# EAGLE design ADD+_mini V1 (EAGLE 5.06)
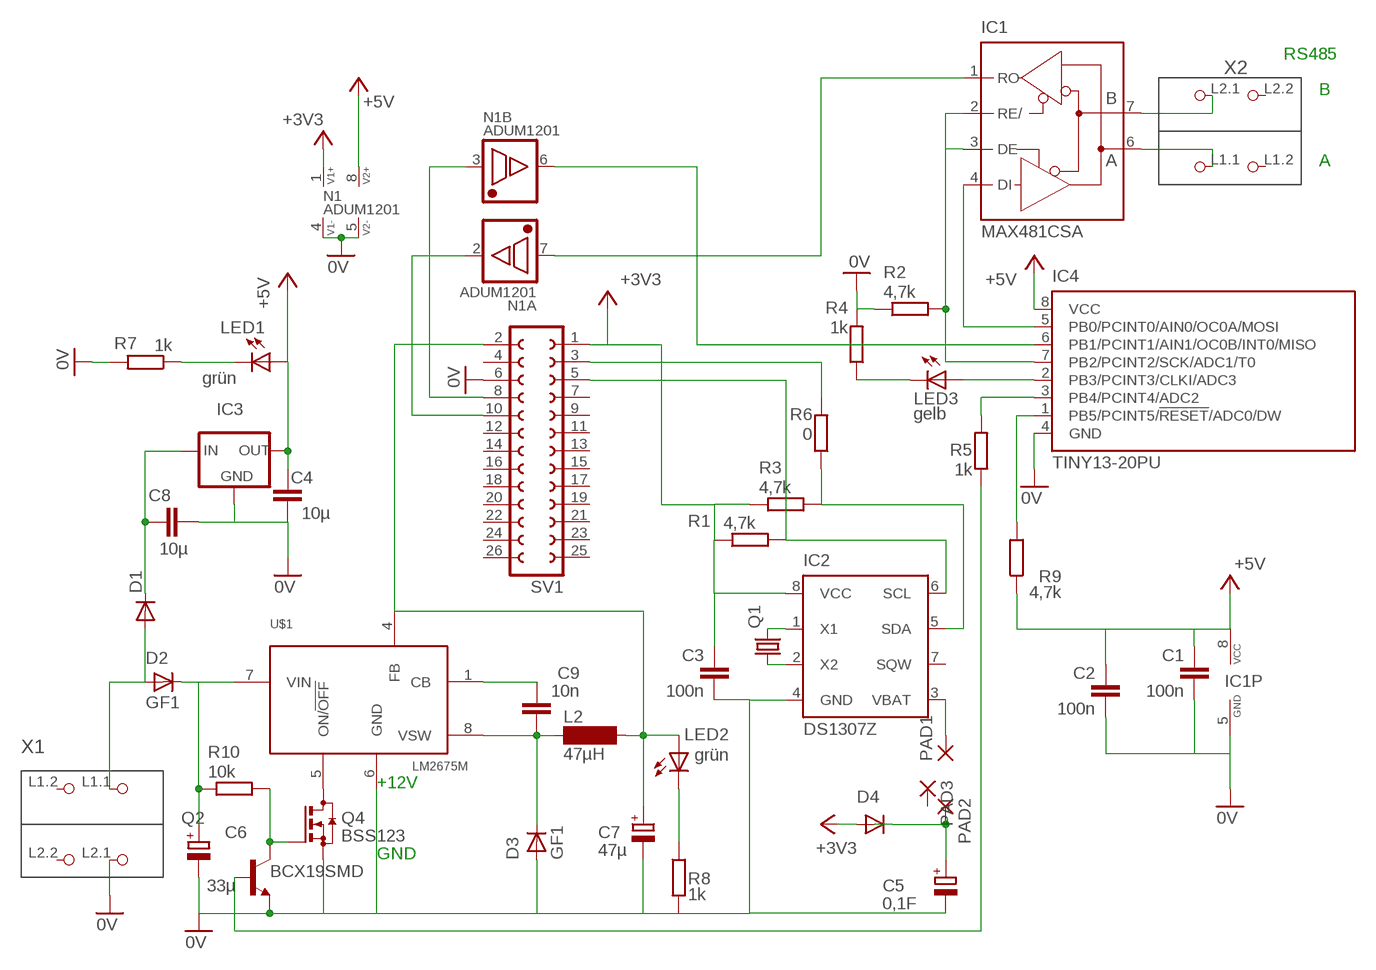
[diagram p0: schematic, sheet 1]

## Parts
C1  100n  C-EUC0603  [C0603]
C2  100n  C-EUC0603  [C0603]
C3  100n  C-EUC1206  [C1206]
C4  10µ  C-EUC1206K  [C1206K]
C5  0,1F  CPOL-EUE5-13  [E5-13]
C6  33µ  CPOL-EUSMCD  [SMC_D]
C7  47µ  CPOL-EUSMCD  [SMC_D]
C8  10µ  C-EUC1206K  [C1206K]
C9  10n  C-EUC0603  [C0603]
D1  DIODE-SOD323-W  [SOD323-W]
D2  GF1  [SMA-DO214AC]
D3  GF1  [SMA-DO214AC]
D4  DIODE-SOD323-W  [SOD323-W]
IC1  MAX481CSA  [SO08]
IC2  DS1307Z  [SOIC8]
IC3  78XXS  [78XXS]
IC4  TINY13-20PU  [DIL08]
L2  47µH  BS11  [BS11]
LED1  grün  LEDCHIPLED_0603  [CHIPLED_0603]
LED2  grün  LEDCHIPLED_0603  [CHIPLED_0603]
LED3  gelb  LEDCHIPLED_0603  [CHIPLED_0603]
N1  ADUM1201  [SO08]
PAD1  2,15/1,0  [2,15/1,0]
PAD2  2,15/1,0  [2,15/1,0]
PAD3  2,15/1,0  [2,15/1,0]
Q1  CRYSTALTC38H  [TC38H]
Q2  BCX19SMD  [SOT23-BEC]
Q4  BSS123  [SOT23]
R1  4,7k  R-EU_R0603  [R0603]
R2  4,7k  R-EU_R0603  [R0603]
R3  4,7k  R-EU_R0603  [R0603]
R4  1k  R-EU_R0603  [R0603]
R5  1k  R-EU_R0603  [R0603]
R6  0  R-EU_R1206  [R1206]
R7  1k  R-EU_R0603  [R0603]
R8  1k  R-EU_R0603  [R0603]
R9  4,7k  R-EU_R0603  [R0603]
R10  10k  R-EU_R0603  [R0603]
SV1  FE13-2  [FE13-2]
U$1  LM2675M  [SO08]
X1  2060-402/998-404  [P-2060-402/998-404]
X2  2060-402/998-404  [P-2060-402/998-404]

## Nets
0V: C1.2 C2.2 C3.2 C4.2 C5.- C6.- C7.- C8.1 D3.A IC1.5(GND) IC2.4(GND) IC3.GND IC4.4(GND) N1.4(P:V1-) N1.5(P:V2-) Q2.E Q4.2(S) R2.1 R4.2 R7.2 R8.2 SV1.6 U$1.6(GND) X1.L2.1(P2.1)
+3V3: C3.1 D4.A IC2.8(VCC) N1.1(P:V1+) R1.1 R3.1 SV1.1
+5V: C1.1 C2.1 C4.1 IC1.8(VCC) IC3.OUT IC4.8(VCC) LED1.A N1.8(P:V2+) R9.1
N$2: D1.A D2.A X1.L1.1(P1.1)
N$3: C5.+ D4.C PAD2.1(P)
N$4: IC2.2(X2) Q1.1
N$6: IC1.1(RO) N1.7(A:IN)
N$7: C6.+ D2.K(C) R10.2 U$1.7(VIN)
N$8: Q4.3(D) U$1.5(ON/!OFF)
N$9: IC2.5(SDA) R3.2 R6.1
N$10: C8.2 D1.C IC3.IN
N$11: IC2.6(SCL) R1.2 SV1.5
N$12: IC2.1(X1) Q1.2
N$13: IC4.6(PB1/PCINT1/AIN1/OC0B/INT0/MISO) N1.6(B:OUT)
N$14: IC1.4(DI) IC4.5(PB0/PCINT0/AIN0/OC0A/MOSI)
N$15: IC1.2(RE/) IC1.3(DE) IC4.7(PB2/PCINT2/SCK/ADC1/T0) R2.2
N$16: LED2.C R8.1
N$17: R6.2 SV1.3
N$18: IC1.7(B) X2.L2.1(P2.1)
N$19: IC4.3(PB4/PCINT4/ADC2) R5.2
N$20: IC4.1(PB5/PCINT5/!RESET!/ADC0/DW) R9.2
N$21: Q2.B R5.1
N$22: N1.2(A:OUT) SV1.10
N$23: N1.3(B:IN) SV1.8
N$24: IC2.3(VBAT) PAD1.1(P)
N$25: Q2.C Q4.1(G) R10.1
N$26: IC1.6(A) X2.L1.1(P1.1)
N$28: C9.2 D3.K(C) L2.1 U$1.8(VSW)
N$29: LED1.C R7.1
N$30: C9.1 U$1.1(CB)
N$31: C7.+ L2.2 LED2.A SV1.2 U$1.4(FB)
N$32: IC4.2(PB3/PCINT3/CLKI/ADC3) LED3.A
N$33: LED3.C R4.1
Unconnected: IC2.7(SQW) PAD3.1(P) SV1.4 SV1.7 SV1.9 SV1.11 SV1.12 SV1.13 SV1.14 SV1.15 SV1.16 SV1.17 SV1.18 SV1.19 SV1.20 SV1.21 SV1.22 SV1.23 SV1.24 SV1.25 SV1.26 X1.L1.2(P1.2) X1.L2.2(P2.2) X2.L1.2(P1.2) X2.L2.2(P2.2)

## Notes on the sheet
- RS485
- B
- A
- +12V
- GND

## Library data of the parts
C1-C4 C8 C9 = rcl:C-EU: CAPACITOR, European symbol
C5-C7 = rcl:CPOL-EU: POLARIZED CAPACITOR, European symbol
D1 D4 = diode:DIODE-: DIODE
D2 D3 = diode:GF1: DIODE
IC1 = maxim:MAX481CSA: RS485 TRANSEIVER
IC2 = ds1307_pcf8583:DS1307: I2C-Bus CLOCK/CALENDAR
IC3 = LM2675:78XXS: VOLTAGE REGULATOR
IC4 = atmel:TINY13: 8-bit AVR Microcontroller with 1K Bytes In-System Programmable Flash Source: http://www.atmel.com/dyn/resources/prod_documents/2535S.pdf
L2 = inductor-neosid:BS: INDUCTOR
LED1-LED3 = led:LED: LED
N1 = digital:ADUM1201: ADuM1400: 1+1 channel digital isolator (Analog Devices) +5V, 1Mbps
PAD1-PAD3 = wirepad:2,15/1,0: THROUGH-HOLE PAD
Q1 = crystal:CRYSTAL: CRYSTAL
Q2 = transistor-npn:BCX19*: NPN Transistor
Q4 = transistor-small-signal:BSS123: N-CHANNEL MOS FET
R1-R10 = rcl:R-EU_: RESISTOR, European symbol
SV1 = con-lsta:FE13-2: FEMALE HEADER
U$1 = Labor:LM2675: SIMPLE SWITCHER ® Power Converter High Efficiency 1A Step-Down Voltage Regulator General Description The LM2675 series of regulators are monolithic integrated circuits built with a LMDMOS process. These regulators provide all the active functions for a step-down (buck) switching regulator, capable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
X1 X2 = con-wago_2060:2060-402/998-404: Serie 2060, SMD-Leiterplattenklemme mit Betätigungsdrückern im Gurt 2-polig / Series 2060, SMD terminal block with push-buttons in tape-and-reel packing 2-pole Polzahl / Pole No.: 2 Bemessungsspannung / Rated Voltage: 160 V Nennstrom / Nominal Current: 9 A Leiterquerschnitt / Conductor Size: 0.2 -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

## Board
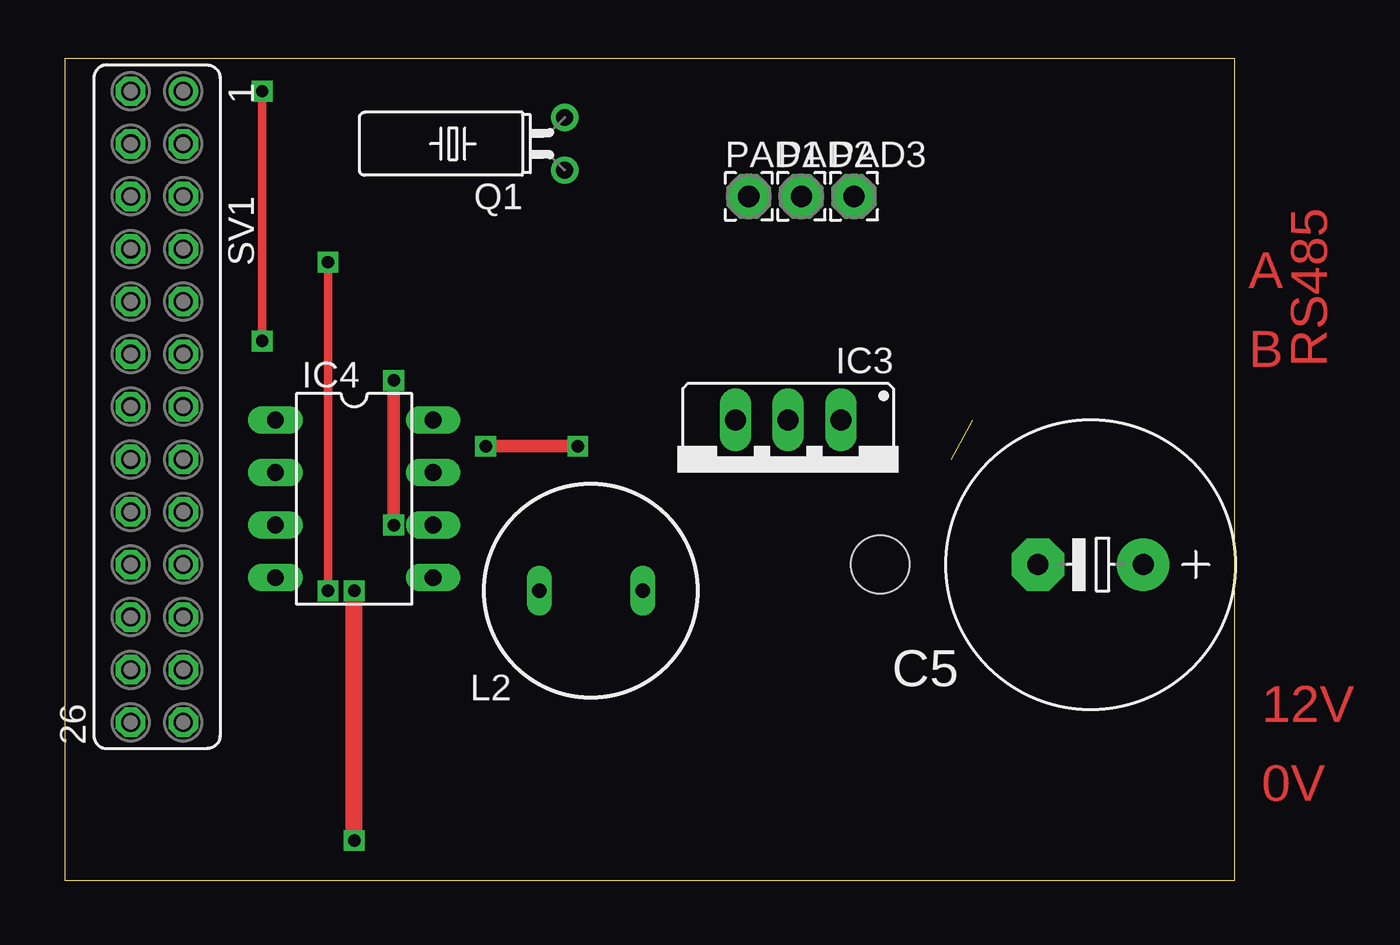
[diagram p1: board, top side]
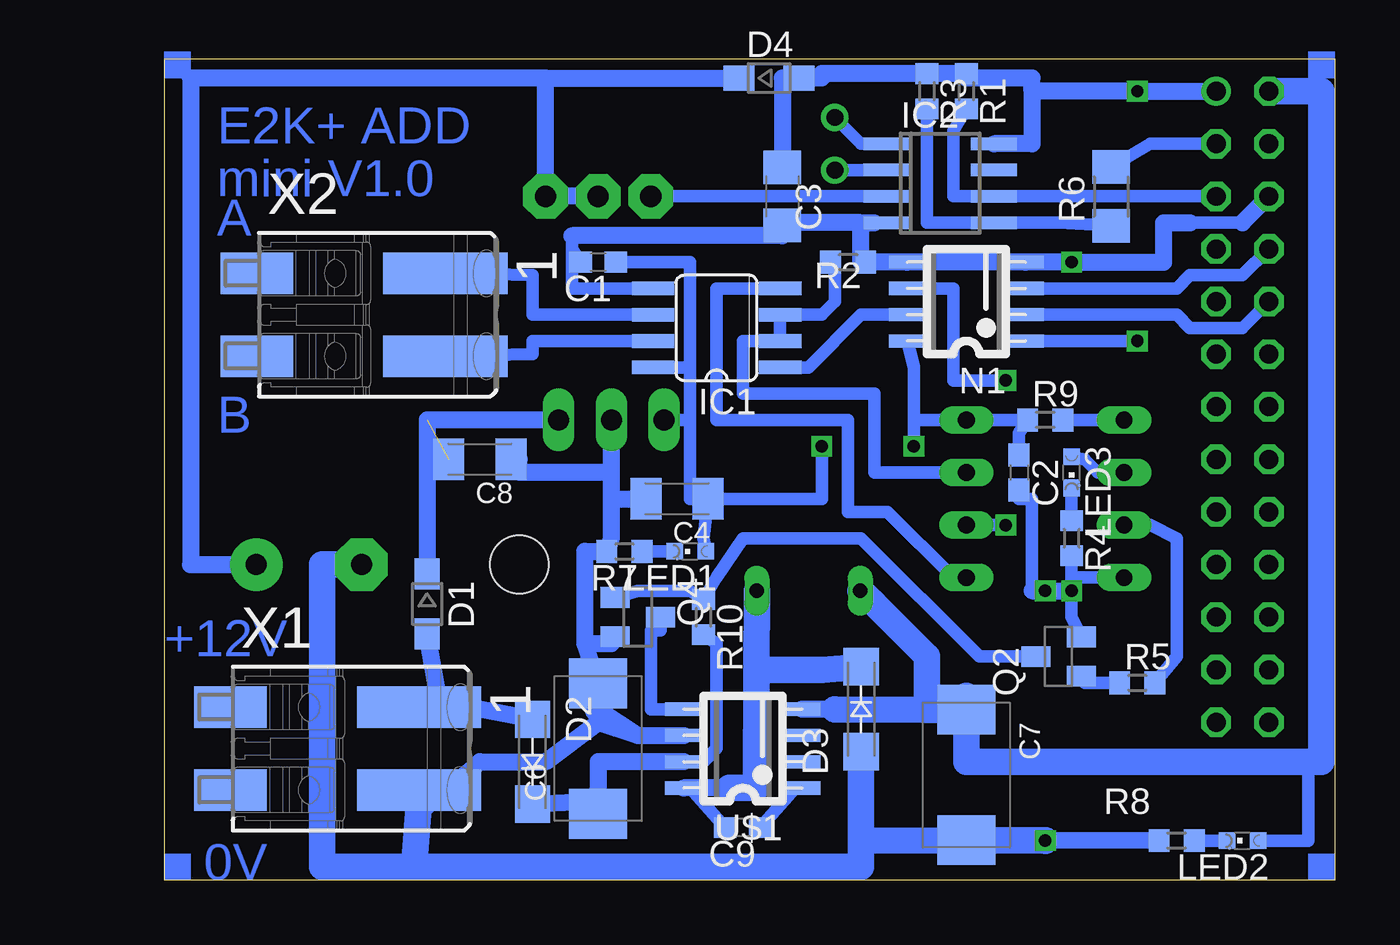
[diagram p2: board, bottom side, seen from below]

Size 56.49 x 39.68 mm. Coordinates in mm from the lower left corner, seen from the top.
Outline: 0,0 56.49,0 56.49,39.68 0,39.68 0,0
Copper layers (1*16): Top 0.035mm / dielectric 1.5mm / Bottom 0.035mm
Design rules "default": minimum track width 10mil, minimum drill 24mil, track to track 8mil, track to pad 8mil, pad to pad 8mil, via to via 8mil, smd to smd 8mil, copper to edge 40mil, drill to drill 8mil, minimum pad ring 10mil, minimum via ring 8mil, stop-mask expansion 4mil, vias tented up to drill 0mil, thermal gap 10mil
Holes 2.8 mm at 39.37,15.24

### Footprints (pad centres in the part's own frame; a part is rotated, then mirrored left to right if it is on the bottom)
C0603 = smd 1.1 x 1: 1 -0.85,0; 2 0.85,0
C1206 = smd 1.6 x 1.8: 1 -1.4,0; 2 1.4,0
C1206K = smd 1.5 x 2: 1 -1.5,0; 2 1.5,0
E5-13 = drill 1.016 pad 2.54 round: + -2.54,0 | drill 1.016 pad 2.54 octagon: - 2.54,0
SMC_D = smd 2.4 x 2.8: + -3.15,0; - 3.15,0
SOD323-W = smd 1.5 x 1.2: A 1.45,0; C -1.45,0
SMA-DO214AC = smd 1.8 x 1.7: A -2.05,0; K 2.05,0
SO08 = smd 0.66 x 2.032: 1 -1.905,-3.073; 2 -0.635,-3.073; 3 0.635,-3.073; 4 1.905,-3.073; 5 1.905,3.073; 6 0.635,3.073; 7 -0.635,3.073; 8 -1.905,3.073
SOIC8 = smd 0.6 x 2.2: 1 -1.905,-2.6; 2 -0.635,-2.6; 3 0.635,-2.6; 4 1.905,-2.6; 5 1.905,2.6; 6 0.635,2.6; 7 -0.635,2.6; 8 -1.905,2.6
78XXS = drill 1.016 long: GND 0,-2.54; IN -2.54,-2.54; OUT 2.54,-2.54
DIL08 = drill 0.813 long: 1 -3.81,-3.81; 2 -1.27,-3.81; 3 1.27,-3.81; 4 3.81,-3.81; 5 3.81,3.81; 6 1.27,3.81; 7 -1.27,3.81; 8 -3.81,3.81
BS11 = drill 0.7 long: 1 -2.5,0; 2 2.5,0
CHIPLED_0603 = smd 0.8 x 0.8: A 0,-0.75; C 0,0.75
SO08' = smd 0.635 x 1.778: 1 -1.905,-2.857; 2 -0.635,-2.857; 3 0.635,-2.857; 4 1.905,-2.857; 5 1.905,2.857; 6 0.635,2.857; 7 -0.635,2.857; 8 -1.905,2.857
2,15/1,0 = drill 1.016 pad 2.159 octagon: 1 0,0
TC38H = drill 0.813 round: 1 -1.27,0; 2 1.27,0
SOT23-BEC = smd 1 x 1.4: B -0.95,-1.1; C 0,1.1; E 0.95,-1.1
SOT23 = smd 1 x 1.4: 1 -0.95,-1.1; 2 0.95,-1.1; 3 0,1.1
R0603 = smd 1 x 1.1: 1 -0.85,0; 2 0.85,0
R1206 = smd 1.6 x 1.803: 1 -1.422,0; 2 1.422,0
FE13-2 = drill 0.914 round: 1 -15.24,1.27 | drill 0.914 octagon: 2 -15.24,-1.27; 3 -12.7,1.27; 4 -12.7,-1.27; 5 -10.16,1.27; 6 -10.16,-1.27; 7 -7.62,1.27; 8 -7.62,-1.27; 9 -5.08,1.27; 10 -5.08,-1.27; 11 -2.54,1.27; 12 -2.54,-1.27; 13 0,1.27; 14 0,-1.27; 15 2.54,1.27; 16 2.54,-1.27; 17 5.08,1.27; 18 5.08,-1.27; 19 7.62,1.27; 20 7.62,-1.27; 21 10.16,1.27; 22 10.16,-1.27; 23 12.7,1.27; 24 12.7,-1.27; 25 15.24,1.27; 26 15.24,-1.27
P-2060-402/998-404 = smd 6 x 2: L1.1 4.05,2; L2.1 4.05,-2 | smd 3.5 x 2: L1.2 -5.05,2; L2.2 -5.05,-2

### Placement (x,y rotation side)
C1  35.56,29.85 180 bottom
C2  15.24,19.69 270 bottom
C3  26.67,33.02 270 bottom
C4  31.75,18.42 180 bottom
C5  49.53,15.24 180 top
C6  35.56,6.35 90 bottom
C7  17.78,5.08 270 bottom
C8  41.27,20.32 180 bottom
C9  28.58,2.54 180 bottom
D1  43.81,13.33 270 bottom
D2  38.73,5.71 270 bottom
D3  22.86,8.25 90 bottom
D4  27.31,38.73 0 bottom
IC1  29.85,26.67 90 bottom
IC2  19.05,33.66 270 bottom
IC3  34.92,19.69 180 top
IC4  13.97,18.42 270 top
L2  25.4,13.97 180 top
LED1  31.12,15.88 90 bottom
LED2  4.45,1.91 90 bottom
LED3  12.7,19.69 180 bottom
N1  ADUM1201  [SO08']  17.78,27.94 90 bottom
PAD1  33.02,33.02 0 top
PAD2  35.56,33.02 0 top
PAD3  38.1,33.02 0 top
Q1  24.13,35.56 90 top
Q2  13.33,10.79 90 bottom
Q4  33.66,12.7 270 bottom
R1  17.78,38.1 270 bottom
R2  23.5,29.85 180 bottom
R3  19.69,38.1 270 bottom
R4  12.7,16.51 270 bottom
R5  9.53,9.53 0 bottom
R6  10.79,33.02 90 bottom
R7  34.29,15.88 180 bottom
R8  7.62,1.91 180 bottom
R9  13.97,22.23 0 bottom
R10  30.48,12.7 270 bottom
SV1  4.45,22.86 270 top
U$1  LM2675M  [SO08']  28.58,6.35 90 bottom
X1  48.26,6.35 0 bottom
X2  46.99,27.3 0 bottom

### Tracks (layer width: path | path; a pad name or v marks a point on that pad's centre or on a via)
0V  (via drill 0.6)
  Top 0.406: v12.7,13.97 v12.7,29.85
  Top 0.813: v13.97,1.91 v13.97,13.97
  Bottom 0.406: Q4.2 34.92,11.75 34.92,11.43
  Bottom 0.61: C3.2 26.67,31.12 | 22.23,31.75 IC2.4 | IC1.5 36.83,28.58 36.83,30.48 | 36.83,31.12 36.83,30.48 | 12.7,14.6 v12.7,13.97 12.7,12.7 Q2.E | 12.7,14.6 IC4.4 | 12.7,14.6 R4.2 | 6.98,31.75 4.45,31.75 | 14.61,13.97 14.61,18.42 15.24,18.42 C2.2 | 36.83,30.48 C1.2
  Bottom 0.813: 22.86,31.75 22.23,31.75 | 4.45,31.75 SV1.6 | 6.98,31.75 8.26,31.75 8.26,29.85 v12.7,29.85 | R8.2 13.97,1.92 | v12.7,13.97 14.61,13.97 v13.97,13.97 | 33.66,6.99 35.56,8.25 | 33.66,6.99 U$1.6 | 33.66,6.99 35.56,7.62 38.1,5.71 41.27,5.71 44.25,3.21 | v12.7,29.85 N1.4 | N1.4 N1.5 R2.1 22.86,29.85 22.86,31.75 | 26.67,31.12 36.83,31.12 | v12.7,29.85 N1.4 | 22.86,31.75 26.67,31.75 C3.2 | 34.92,18.42 34.92,19.69 | 34.92,19.69 IC3.GND | 34.92,18.42 C4.2 | C8.1 39.37,20.32 39.37,19.69 34.92,19.69 | 34.92,18.42 34.92,16.51 R7.2 36.2,15.88 36.2,11.43 | C6.- 36.2,11.43 | 36.2,11.43 34.92,11.43
  Bottom 1.27: 22.86,1.91 C7.- 13.97,1.92 v13.97,1.91 | 22.86,1.91 D3.A | 22.86,1.91 22.86,0.64 43.81,0.64 | 43.81,0.64 44.45,0.64 44.25,3.21 X1.L2.1 | C5.- 48.89,15.24 48.89,0.64 43.81,0.64 | 35.56,8.25 C6.-
+3V3  (via drill 0.6)
  Top 0.406: v9.53,26.04 v9.53,38.1
  Bottom 0.61: v9.53,26.04 N1.1
  Bottom 0.813: SV1.1 v9.53,38.1 14.61,38.1 | 14.61,38.1 14.61,35.56 IC2.8 | 14.61,38.1 14.61,38.73 17.78,38.73 R1.1 R3.1 24.77,38.95 24.77,38.73 D4.A 26.67,38.73 C3.1
+5V  (via drill 0.6)
  Top 0.61: v20.32,20.96 v24.77,20.96
  Bottom 0.61: 31.12,24.77 IC1.8 | C1.1 31.12,29.85 31.12,24.77 | 31.12,22.23 31.12,18.42 C4.1 | 31.12,22.23 31.12,24.77 | 31.12,22.23 IC3.OUT | C2.1 15.24,21.59 R9.1 IC4.8 20.32,22.23 | N1.8 20.32,24.77 20.32,22.23 | 20.32,22.23 v20.32,20.96 | v24.77,20.96 24.77,18.42 C4.1 | LED1.A 30.48,16.51 C4.1
N$2
  Bottom 0.813: 43.18,8.25 D1.A | 43.18,8.25 X1.L1.1 | D2.A 41.27,8.25 43.18,8.25
N$3
  Bottom 0.813: 38.1,38.73 55.24,38.73 55.24,15.24 C5.+ | 38.1,38.73 38.1,33.02 PAD2.1 | 38.1,38.73 D4.C
N$4
  Bottom 0.61: IC2.2 Q1.1
N$6
  Bottom 0.61: IC1.1 26.04,24.77 | IC1.1 27.31,24.77 | N1.7 22.86,27.3 25.4,24.77 IC1.1
N$7
  Bottom 0.61: U$1.7 30.48,5.71 29.85,6.35 29.85,11.43 R10.2
  Bottom 0.813: D2.K 35.56,3.81 C6.+ | C6.+ 35.56,4.45 | U$1.7 35.56,5.71 C6.+
N$8
  Bottom 0.61: U$1.5 33.02,8.25 33.02,12.06 32.55,12.06 Q4.3
N$9
  Bottom 0.61: R6.1 13.33,31.75 IC2.5 19.69,31.75 R3.2
N$10  (1 unrouted)
  Bottom 0.813: IC3.IN 43.81,22.23 D1.C
N$11
  Bottom 0.61: SV1.5 IC2.6 18.42,33.02 18.42,36.2 R1.2
N$12
  Bottom 0.61: IC2.1 22.86,35.56 Q1.2
N$13  (via drill 0.6)
  Top 0.61: v15.88,17.14 v15.88,24.13
  Bottom 0.61: N1.6 18.42,28.58 18.42,24.13 v15.88,24.13 | IC4.6 v15.88,17.14
N$14
  Bottom 0.61: IC1.4 29.85,28.58 29.85,22.23 23.5,22.23 23.5,17.78 21.59,17.78 18.42,14.6 IC4.5
N$15
  Bottom 0.61: IC4.7 22.23,19.69 22.23,23.5 28.58,23.5 28.58,26.04 IC1.2 IC1.3 24.77,27.3 24.13,27.94 24.13,29.21 R2.2
N$16
  Bottom 0.61: LED2.C R8.1
N$17
  Bottom 0.61: SV1.3 8.89,35.56 R6.2
N$18
  Bottom 0.61: IC1.7 38.73,26.04 38.73,25.4 X2.L2.1
N$19
  Bottom 0.61: IC4.3 8.89,17.14 7.62,16.51 7.62,10.79 R5.2
N$20
  Bottom 0.61: IC4.1 R9.2
N$21
  Bottom 0.61: R5.1 12.06,9.53 Q2.B
N$22
  Bottom 0.61: SV1.10 4.45,26.67 6.98,26.67 7.62,27.3 N1.2
N$23
  Bottom 0.61: SV1.8 4.45,29.21 6.98,29.21 7.62,28.58 N1.3
N$24
  Bottom 0.61: IC2.3 PAD1.1
N$25
  Bottom 0.61: Q2.C 17.15,10.79 22.86,16.51 28.58,16.51 29.85,14.6 R10.1 31.12,13.97 33.66,13.97 Q4.1
N$26
  Bottom 0.61: IC1.6 38.73,27.3 38.73,29.21 X2.L1.1
N$28
  Bottom 0.61: U$1.8 31.12,4.45 C9.2
  Bottom 0.813: 29.21,4.45 U$1.8
  Bottom 1.27: 27.91,10.16 27.94,4.45 29.21,4.45 | 27.91,10.16 L2.1 | D3.K 24.77,10.16 27.91,10.16
N$29
  Bottom 0.61: R7.1 LED1.C
N$30
  Bottom 0.61: U$1.1 26.04,4.45 C9.1
N$31
  Bottom 0.61: LED2.A 1.27,1.91 1.27,5.71
  Bottom 0.813: 24.13,8.25 U$1.4
  Bottom 1.27: SV1.2 0.64,38.1 0.64,5.71 1.27,5.71 17.78,5.71 C7.+ | C7.+ 17.78,8.89 | C7.+ 19.69,8.23 | 19.69,8.23 24.13,8.25 | L2.2 22.23,13.33 19.69,10.79 19.69,8.23
N$32
  Bottom 0.61: IC4.2 11.43,19.69 12.06,20.32 LED3.A
N$33
  Bottom 0.61: R4.1 LED3.C
(copper drawn outside any net)
  shapes: Bottom area x6

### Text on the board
Top: A | B | RS485 | 12V | 0V
Bottom: E2K+ ADD | mini V1.0 | A | B | +12V | 0V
